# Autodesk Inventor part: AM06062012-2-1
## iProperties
Created: 2012-06
Part Number: AM06062012-2-1
Material: Polycarbonate, Clear
Document SubType Name: Modeling
Designer: Administrator
Mass: 4838.8 g
Surface Area: 14622 cm^2
Volume: 4032.33 cm^3
Density: 1.2 g/cm^3
Stock Number: 21.1830  1/4" CLEAR POLYCARBONATE
Author: Administrator
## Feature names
1. Extrusion1
2. ROLLER MTG HOLES [Hole]
3. BULLET CATCH MTG HOLES [Hole]
4. HANDLE MTG HOLES [Hole]
